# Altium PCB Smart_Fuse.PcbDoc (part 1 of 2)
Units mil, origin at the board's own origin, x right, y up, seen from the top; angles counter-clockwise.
Board outline 4000 x 2763 mil, 4 copper layers (Top Layer, Signal Layer 1, Signal Layer 2, Bottom Layer), stack 61.6 mil thick; 113 components, 65 nets, 281 pads, 450 vias.
Unrouted connection lines stored in the file: 2.
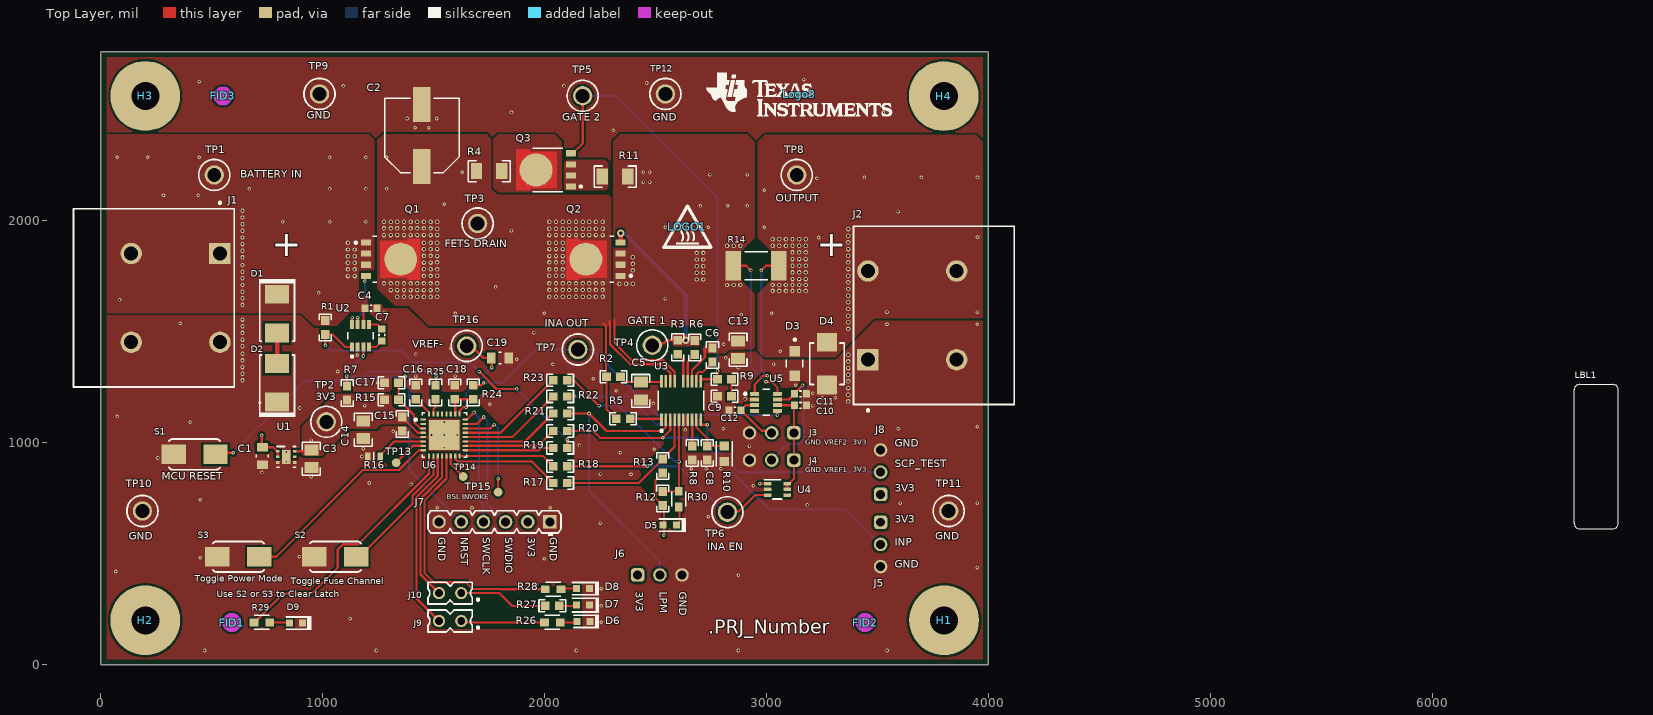
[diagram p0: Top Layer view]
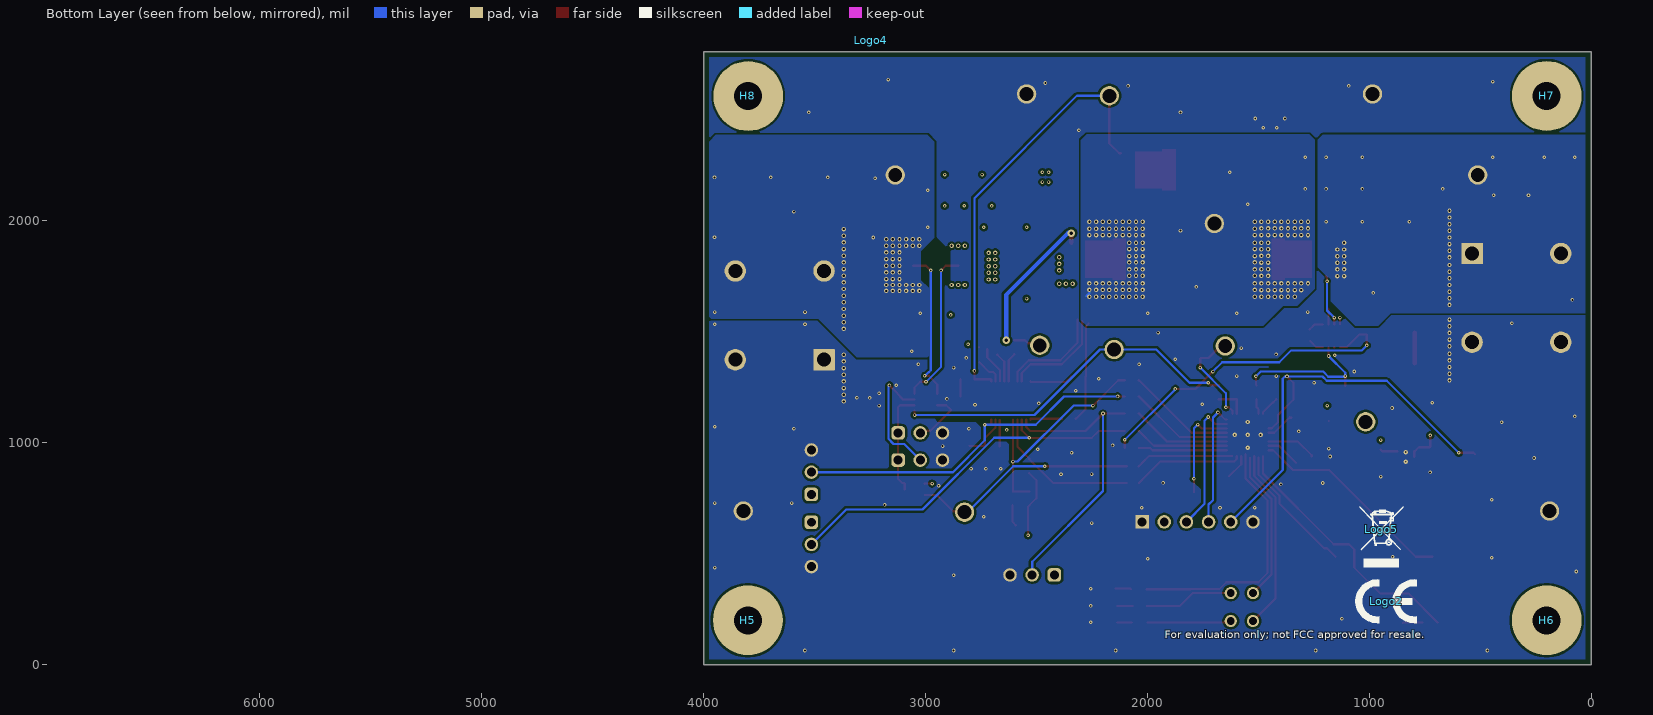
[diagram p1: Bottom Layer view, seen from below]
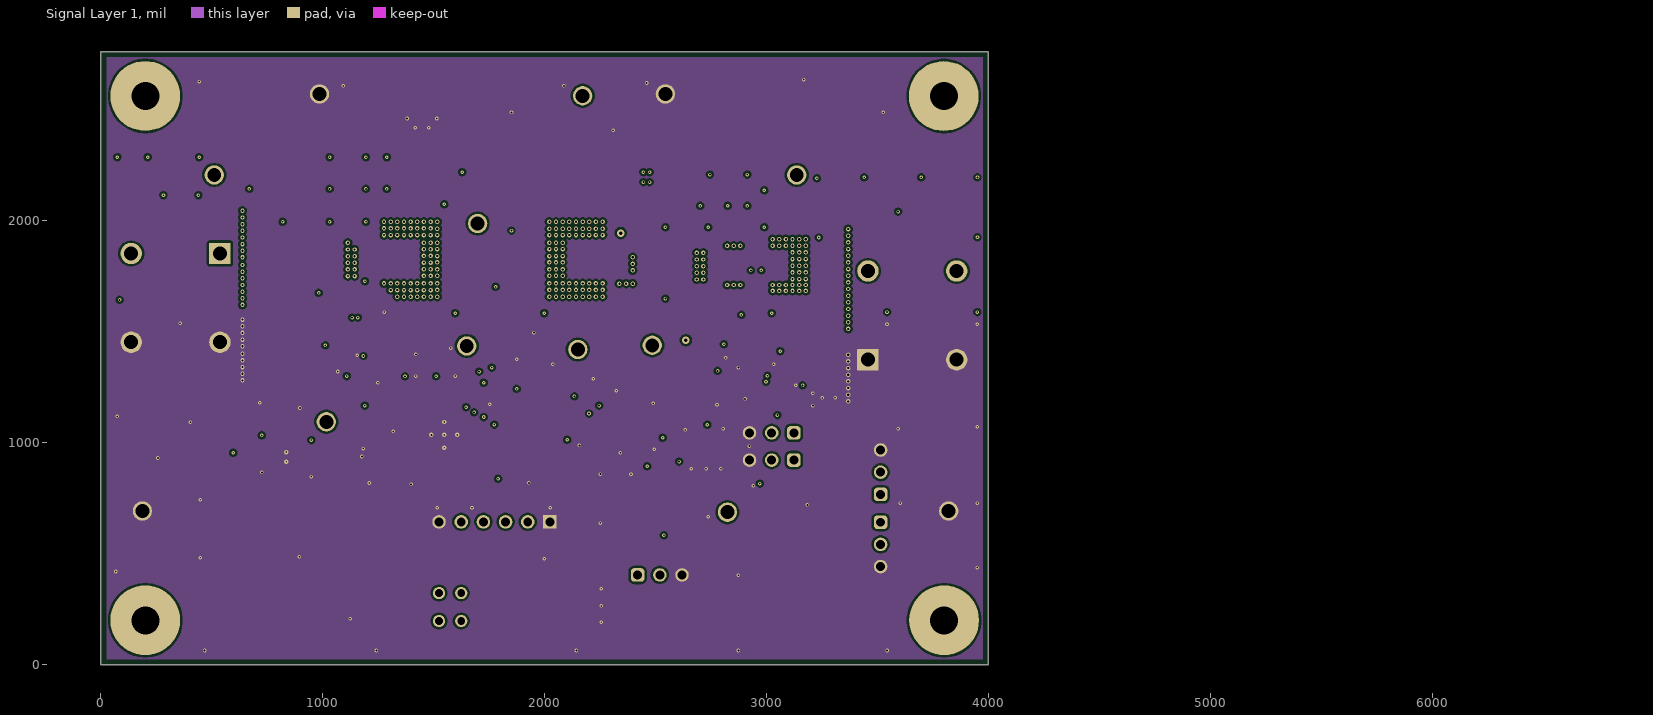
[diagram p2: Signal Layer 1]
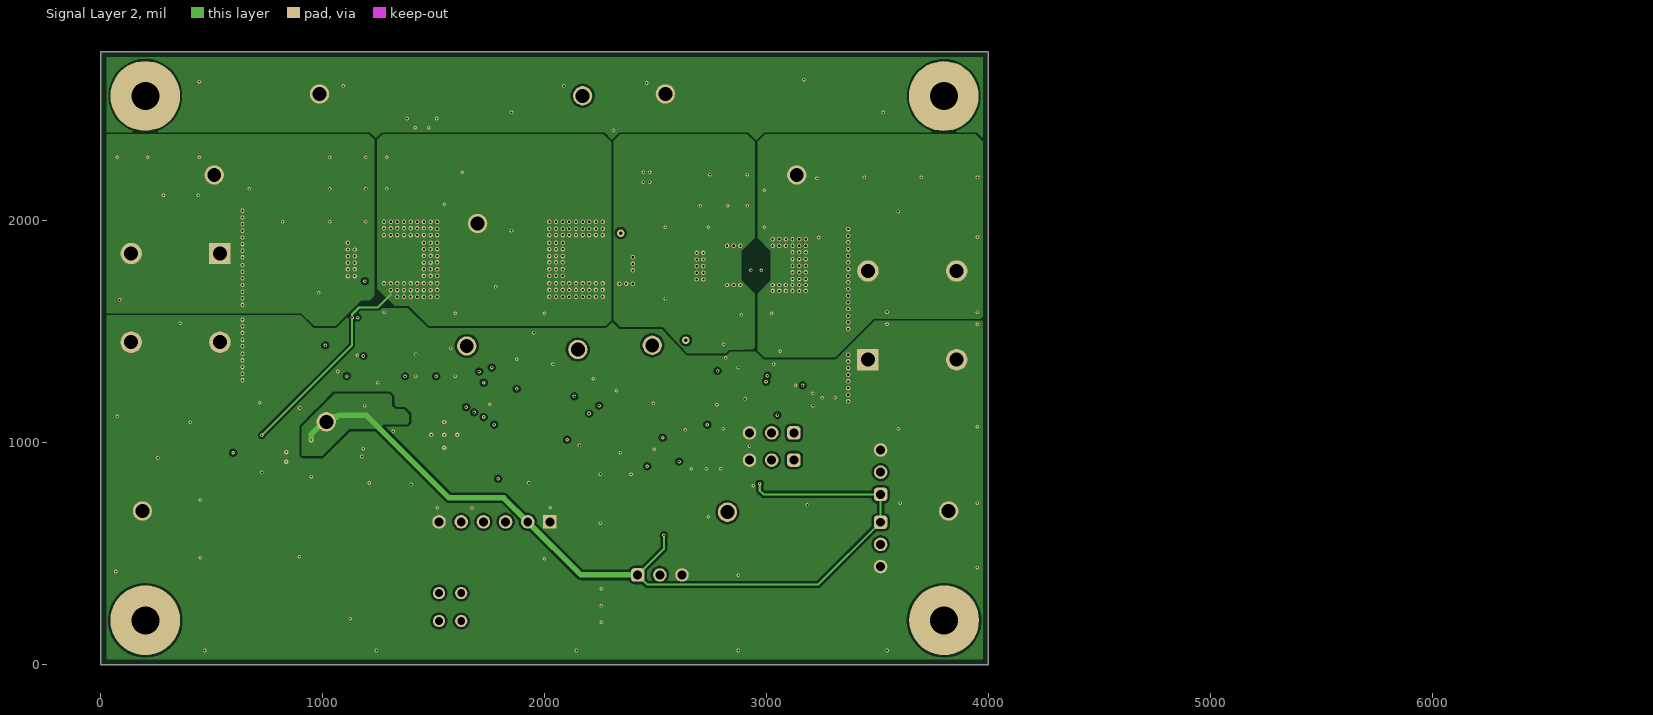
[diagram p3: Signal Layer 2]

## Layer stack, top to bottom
Top Solder: solder mask 0.4, Solder Resist, Dk 3.5
Top Layer: signal copper 2.8
Dielectric 1: prepreg 8, FR-4 High Tg, Dk 4.2
Signal Layer 1: signal copper 1.4
Dielectric 2: core 37.2, FR-4 High Tg, Dk 4.2
Signal Layer 2: signal copper 1.4
Dielectric 3: prepreg 8, FR-4 High Tg, Dk 4.2
Bottom Layer: signal copper 2.8
Bottom Solder: solder mask 0.4, Solder Resist, Dk 3.5

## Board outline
0,0 4000,0 4000,2763 0,2763

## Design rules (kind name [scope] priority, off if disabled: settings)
AcuteAngle [All] p1: minimum=4.50000000000000E+0001 checktracksonly=FALSE
AssemblyTestPointUsage [All] p1: valid=2
BoardOutlineClearance BoardOutlineClearance_MountingHoles [OnCopper and InComponentClass('Mounting Holes')] p1: gap=39.37 ignorepadtopadclearanceinfootprint=FALSE
BoardOutlineClearance BoardOutlineClearance_Poly [OnCopper and IsPoly] p2: gap=25 ignorepadtopadclearanceinfootprint=FALSE
BoardOutlineClearance [OnCopper and Not InComponentClass('Logo') and not InComponentClass('FiducialMark') and not InRegion(1000,500,4000,800) and not InPoly] p3: gap=40 ignorepadtopadclearanceinfootprint=FALSE
Clearance Clearance_Keepouts [((IsTrack Or IsArc) And Not InPoly) And IsFree and IsKeepOut vs ((IsTrack Or IsArc) And Not InPoly) And IsFree and IsKeepOut] p1: gap=0 ignorepadtopadclearanceinfootprint=FALSE
Clearance Clearance_Poly [InPolygon] p2: gap=10 ignorepadtopadclearanceinfootprint=TRUE
Clearance Clearance_FiducialMark [IsKeepOut and InComponentClass('FiducialMark') vs IsPad and InComponentClass('FiducialMark')] p3: gap=0 ignorepadtopadclearanceinfootprint=FALSE
Clearance [All] p4: gap=7.87 ignorepadtopadclearanceinfootprint=TRUE
ComponentClearance ComponentClearance_MountingHoles_FiducialMarks [InComponentClass('Mounting Holes') vs InComponentClass('FiducialMark')] p1: gap=50 collisioncheckmode=3 verticalgap=10 showdistances=FALSE
ComponentClearance ComponentClearance_Shunt [InComponentClass('Header') vs InComponentClass('Shunt')] p2: gap=0 collisioncheckmode=3 verticalgap=0 showdistances=FALSE
ComponentClearance ComponentClearance_Logo [InComponentClass('Logo')] p3: gap=30 collisioncheckmode=3 verticalgap=10 showdistances=FALSE
ComponentClearance ComponentClearance_ScrewToNut [(HasFootprint('NY PMS 440 0025 PH')) vs (HasFootprint('Keystone_1902C'))] p4: gap=5 collisioncheckmode=3 verticalgap=10 showdistances=FALSE
ComponentClearance ComponentClearance_MountingHoles [InComponentClass('Mounting Holes')] p5: gap=100 collisioncheckmode=3 verticalgap=100000 showdistances=FALSE
ComponentClearance ComponentClearance_SmallPassives [HasFootprint('0201*') or HasFootprint('0402*') or HasFootprint('0508') or HasFootprint('0603*') or HasFootprint('0612') or HasFootprint('0805*') or HasFootprint('0815*') or HasFootprint('0830*') or HasFootprint('1206*') or HasFootprint('1210*') or HasFootprint('1808*') or HasFootprint('1812*') or HasFootprint('1825*') or HasFootprint('2010*') or HasFootprint('2220*') or HasFootprint('2225*') or HasFootprint('2512*') or HasFootprint('2728*') or HasFootprint('3518*') vs HasFootprint('0201*') or HasFootprint('0402*') or HasFootprint('0508') or HasFootprint('0603*') or HasFootprint('0612') or HasFootprint('0805*') or HasFootprint('0815*') or HasFootprint('0830*') or HasFootprint('1206*') or HasFootprint('1210*') or HasFootprint('1808*') or HasFootprint('1812*') or HasFootprint('1825*') or HasFootprint('2010*') or HasFootprint('2220*') or HasFootprint('2225*') or HasFootprint('2512*') or HasFootprint('2728*') or HasFootprint('3518*')] p6: gap=14.96 collisioncheckmode=3 verticalgap=10 showdistances=FALSE
ComponentClearance ComponentClearance_THtoSMT [IsThruComponent vs IsSMTComponent] p7: gap=30 collisioncheckmode=3 verticalgap=30 showdistances=FALSE
ComponentClearance ComponentClearance_THtoTH [IsThruComponent vs IsThruComponent] p8: gap=20 collisioncheckmode=3 verticalgap=30 showdistances=FALSE
ComponentClearance [All] p9: gap=20 collisioncheckmode=3 verticalgap=10 showdistances=FALSE
DiffPairsRouting [All] p1: maxlimit=100 minlimit=10 mostfreqgap=10 toplayer_minwidth=15 toplayer_maxwidth=15 toplayer_prefwidth=15 midlayer1_minwidth=15 midlayer1_maxwidth=15 midlayer1_prefwidth=15 midlayer2_minwidth=15 midlayer2_maxwidth=15 midlayer2_prefwidth=15 bottomlayer_minwidth=15 bottomlayer_maxwidth=15 bottomlayer_prefwidth=15 maxuncoupledlength=1000
FabricationTestPointUsage TestPointUsage [All] p1: valid=2 allowmultiple=FALSE
FabricationTestpoint Testpoint [All] p1: side=3 testpointundercomponent=TRUE minsize=40 maxsize=100 preferedsize=60 minholesize=0 maxholesize=40 preferedholesize=32 testpointgrid=1 allowsidetop=TRUE allowsidebottom=TRUE usegrid=TRUE gridtolerance=0.01
FanoutControl Fanout_LCC [IsLCC] p1: bgadir=Out bgaviamode=Centered fanoutstyle=Auto fanoutdirection=Alternating viagrid=1 // Fanout_LCC (Default Rule)
FanoutControl Fanout_BGA [IsBGA] p2: bgadir=Out bgaviamode=Centered fanoutstyle=Auto fanoutdirection=Alternating viagrid=1 // Fanout_BGA (Default Rule)
FanoutControl Fanout_Default [All] p4: bgadir=Out bgaviamode=Centered fanoutstyle=Auto fanoutdirection=Alternating viagrid=1 // Fanout_Default (Default Rule)
FanoutControl Fanout_Small [(CompPinCount < 5)] p5: bgadir=Out bgaviamode=Centered fanoutstyle=Auto fanoutdirection=OutThenIn viagrid=1 // Fanout_Small (Default Rule)
HoleSize [All] p1: absolutevalues=TRUE maxlimit=251 minlimit=7.87 maxpercent=80.000 minpercent=20.000
MinimumAnnularRing MinimumAnnularRing_ThermalPadVias [IsVia and InAnyComponent] p1: minimumring=5.91
MinimumAnnularRing [All] p2: minimumring=4
MinimumSolderMaskSliver MinimumSolderMaskSliver_Logo [InComponentClass('Logo') vs InComponentClass('Logo')] p1: minsoldermaskwidth=0.7
MinimumSolderMaskSliver [All] p2: minsoldermaskwidth=3.94
PlaneConnect [All] p1: planeconnectstyle=Direct reliefexpansion=10 reliefentries=4 reliefconductorwidth=10 reliefairgap=10
PolygonConnect [All] p1: connectstyle=Direct reliefconductorwidth=10 reliefentries=4 polygonreliefangle="90 Angle" airgapwidth=10
RoutingVias ThermalPadVias [IsVia and InAnyComponent] p1: holewidth=7.87 width=19.68 viastyle="Through Hole" minholewidth=7.87 minwidth=19.68 maxholewidth=12.99 maxwidth=23.62
RoutingVias [All] p2: holewidth=8 width=16 viastyle="Through Hole" minholewidth=7 minwidth=8 maxholewidth=40 maxwidth=65
RoutingVias RoutingVias_1 [All] p3: holewidth=28 width=50 viastyle="Through Hole" minholewidth=28 minwidth=50 maxholewidth=28 maxwidth=50
SilkToBoardRegionClearance [Not ((IsComment or IsDesignator) And (Hide <> 'False')) and not InRegion(1000,500,4000,800)] p1:
SilkToSilkClearance SilkToSilkClearance_Pb-FreeLogo [(HasFootprint('Pb-Free_Overlay_Medium') OR HasFootprint('Pb-Free_Overlay_Small')) vs (HasFootprint('Pb-Free_Overlay_Medium') OR HasFootprint('Pb-Free_Overlay_Small'))] p1: silktosilkclearance=0
SilkToSilkClearance [All] p2: silktosilkclearance=3.94
SilkToSolderMaskClearance SilkToComponentPadClearance [(IsPad or IsFill or IsRegion) and InAnycomponent] p1: minsilkscreentomaskgap=5 clearancetoexposedcopper=TRUE
SilkToSolderMaskClearance "Silk to Solder Mask Opening" [All] p2: minsilkscreentomaskgap=3.94 clearancetoexposedcopper=FALSE
SolderMaskExpansion [All] p1: expansion=1.97 istentingtop=FALSE
UnRoutedNet [All] p1: checkbadconnections=TRUE
Width [All] p1: maxlimit=100 minlimit=6 preferedwidth=10
14 further rules are at their usual default settings.

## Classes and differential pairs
component class Smart_Fuse_Schematic: C1 C2 C3 C4 C5 C6 C7 C8 C9 C10 C11 C12 C13 D1 D2 D3 D4 J1 J2 J3 J4 Q1 Q2 Q3 R1 R2 R3 R4 R5 R6 R7 R8 R9 R10 R11 R12 R13 R14 TP1 TP2 TP3 TP4 TP5 TP6 TP7 TP8 TP9 TP10 TP11 TP12 U1 U2 U3 U4 U5
component class Smart_Fuse_MCU_Schematic: C14 C15 C16 C17 C18 C19 D5 D6 D7 D8 D9 J5 J6 J7 J8 J9 J10 R15 R16 R17 R18 R19 R20 R21 R22 R23 R24 R25 R26 R27 R28 R29 R30 S1 S2 S3 TP13 TP14 TP15 TP16 U6
component class Header: J3 J4 J5 J6 J7 J8 J9 J10
component class "Mounting Holes": H1 H2 H3 H4
component class Logo: Logo3
component class Smart_Fuse_Hardware: FID1 FID2 FID3 H1 H2 H3 H4 H5 H6 H7 H8 LBL1 LOGO1 Logo2 Logo3 Logo4 Logo5
component class FiducialMark: FID1 FID2 FID3
component class Label: LBL1

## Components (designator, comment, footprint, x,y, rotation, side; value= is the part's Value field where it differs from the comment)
C1 "UMK212B7105KGHT" FP-UMK212B7105KGHT_0805-MFG 727.34,940.49 r90 top value=1µF
C2 "EEE-FK1J470P" SM_RADIAL_F 1446.85,2385.26 r90 top value=47uF
C3 "GCM21BD70J226ME36L" 0805_HV 948.19,928.19 r270 top value=22uF
C4 "06035C104K4Z4A" 0603L 1216.7,1606.53 r0 top value=0.1uF
C5 "CGA4J2C0G1H223J125AA" 0805_HV 2433.37,1233.76 r270 top value=0.022uF
C6 "06035C104KAZ2A" 0603 2756.27,1395.43 r270 top value=0.1uF
C7 "06035C104K4Z4A" 0603L 1266.63,1486.16 r270 top value=0.1uF
C8 "06035C104KAZ2A" 0603 2732.84,953.78 r270 top value=0.1uF
C9 "CGA3E2X7R1H473K080AA" 0603 2810.66,1209.78 r180 top value=0.047uF
C10 "06035C104KAZ2A" 0603L 3152.84,1168.36 r180 top value=0.1uF
C11 "GRM188R71C104KA01D" 0603L 3152.84,1220.83 r0 top value=0.1uF
C12 "GRM188R71C104KA01D" 0603L 2857.45,1147.57 r180 top value=0.1uF
C13 "CGA4J2C0G1H223J125AA" 0805_HV 2871.84,1419.41 r270 top value=0.022uF
C14 "JMJ212CB7106KGHT" 0805_HV 1182.26,1058.66 r90 top value=10uF
C15 "06035C104KAZ2A" 0603 1358.01,1084.67 r90 top value=0.1uF
C16 "CGA3E3X7R1H474M080AE" 0603 1418.5,1227.38 r90 top value=0.47uF
C17 "C0603C103J3GECAUTO" 0603 1309.28,1270.56 r180 top value=0.01uF
C18 "06035C104KAZ2A" 0603 1595.22,1227.38 r90 top value=0.1uF
C19 "UMK212B7105KGHT" FP-UMK212B7105KGHT_0805-MFG 1798.93,1382.2 r180 top value=1µF
D1 "SMBJ33A-13-F" SMB 793.92,1582.31 r270 top value=33V
D2 "SMBJ16A-13-F" SMB 793.92,1270.56 r90 top value=16V
D3 "PMEG6020ELRX" FP-PMEG6020ELRX_SOD123W-MFG 3126.68,1357.69 r270 top
D4 "SMBJ36CA" FP-SMBJ36CA_DO-214AA-0 3271.96,1356.55 r90 top
D5 "HSMC-C191" HSMx-C191_Red 2563.69,628.5 r0 top value=Red
D6 "LTST-C191KGKT" LTST-C191_Green 2174.49,194.89 r0 top value=Green
D7 "LTST-C193TBKT-5A" LTST-C193_Blue 2172.52,268.45 r0 top value=Blue
D8 "HSMC-C191" HSMx-C191_Red 2172.52,343.17 r0 top value=Red
D9 "LTST-C191KGKT" LTST-C191_Green 878.55,187.28 r0 top value=Green
FID1 "Fiducial" Fiducial10-20#1 590,190 r90 top
FID2 "Fiducial" Fiducial10-20#2 3444,190 r90 top
FID3 "Fiducial" Fiducial10-20#1 550,2563 r90 top
H1 "NY PMS 440 0025 PH" "NY PMS 440 0025 PH"#1 3800,200 r0 top locked
H2 "NY PMS 440 0025 PH" "NY PMS 440 0025 PH"#1 200,200 r0 top locked
H3 "NY PMS 440 0025 PH" "NY PMS 440 0025 PH"#2 200.87,2563.09 r0 top
H4 "NY PMS 440 0025 PH" "NY PMS 440 0025 PH"#3 3800,2563 r0 top
H5 "1902C" Keystone_1902C 3800,200 r180 bottom locked
H6 "1902C" Keystone_1902C 200,200 r180 bottom locked
H7 "1902C" Keystone_1902C 200,2563 r180 bottom
H8 "1902C" Keystone_1902C 3800,2563 r180 bottom
J1 "691256610002" FP-691256610002_HDR2-MFG 239.15,1653.25 r270 top
J2 "691256610002" FP-691256610002_HDR2-MFG 3754.11,1574.35 r90 top
J3 "TSW-103-07-T-S" Samtec_TSW-103-07-T-S 3023.13,1044.67 r180 top
J4 "TSW-103-07-T-S" Samtec_TSW-103-07-T-S 3023.13,922.28 r180 top
J5 "TSW-103-07-T-S" Samtec_TSW-103-07-T-S 3514,542 r270 top
J6 "TSW-103-07-T-S" Samtec_TSW-103-07-T-S 2518.87,404.3 r0 top
J7 "PBC06SAAN" Sullins_PxC06SAAN 1773.8,643.52 r180 top
J8 "TSW-103-07-T-S" Samtec_TSW-103-07-T-S 3514,867.49 r90 top
J9 "SL 11 112 02G" Fischer_SL-11-112-02G 1573.8,196.76 r180 top
J10 "SL 11 112 02G" Fischer_SL-11-112-02G 1573.8,322.67 r180 top
LBL1 "THT-14-423-10" Label_650x200 6739,938 r90 top
LOGO1 "CAUTION HOT SURFACE" IEC_HotSurface_Small 2643.32,1974.33 r0 top
Logo2 "CE Mark" CE_Mark_5mm 924.15,285.69 r180 bottom
Logo3 "Texas Instruments" TI_Stacked_Overlay_Small 3147,2570 r0 top
Logo4 "FCC disclaimer" FCC_disclaimer 3246.69,2814.96 r180 bottom
Logo5 "WEEE logo" WEEE_Minimum 946.02,610.24 r180 bottom
Q1 "BUK7J1R4-40HX" FP-BUK7J1R4-40HX_LFPAK56E-MFG 1317.89,1827.27 r270 top
Q2 "BUK7J1R4-40HX" FP-BUK7J1R4-40HX_LFPAK56E-MFG 2219.09,1827.27 r90 top
Q3 "BUK9Y29-40E,115" FP-BUK9Y29-40E,115_LFPAK56-MFG 2007.78,2229.8 r90 top
R1 "ERJ-3GEY0R00V" 0603 1011.54,1519.79 r90 top value=0
R2 "RMCP0603JT100R" 0603 2310.07,1297.76 r0 top value=100
R3 "ERJ-3GEY0R00V" 0603 2599.52,1430.72 r90 top value=0
R4 "ERJ-8GEY0R00V" 1206 1749.52,2224.48 r180 top value=0
R5 "ERJ-3GEY0R00V" 0603 2353.54,1108.47 r0 top value=0
R6 "ERJ-3GEY0R00V" 0603 2676.11,1429.47 r90 top value=0
R7 "CRCW060314K0FKEA" 0603 1109.45,1224.3 r270 top value=14.0k
R8 "RG1608P-473-B-T5" 0603 2664.82,953.78 r90 top value=47.0k
R9 "CRCW0603220RJNEA" 0603 2810.66,1286.28 r180 top value=220
R10 "ERJ-PB3B1003V" FP-ERJ-PB3B1003V_0603-IPC_A 2809.68,950.68 r270 top value=100k
R11 "CSR1206FKR500" 1206 2317.25,2199.8 r180 top value=0.5
R12 "CRCW060314K0FKEA" 0603 2531.62,748.47 r270 top value=14.0k
R13 "CRCW060314K0FKEA" 0603 2531.62,895.7 r270 top value=14.0k
R14 "WSLF25121L000FEB" FP-WSLF25121L000FEB_2512-MFG 2952.79,1797.74 r180 top
R15 "CRCW060347K0JNEA" 0603 1309.28,1193.89 r180 top value=47k
R16 "ERJ-PB3B1003V" FP-ERJ-PB3B1003V_0603-MFG 1230.63,938.51 r0 top value=100k
R17 "ERJ-3GEY0R00V" 0603 2070,818.83 r180 top value=0
R18 "ERJ-3GEY0R00V" 0603 2070,893.81 r180 top value=0
R19 "ERJ-3GEY0R00V" 0603 2070,976.74 r180 top value=0
R20 "ERJ-3GEY0R00V" 0603 2069.8,1053.17 r180 top value=0
R21 "ERJ-3GEY0R00V" 0603 2069.8,1131.92 r180 top value=0
R22 "ERJ-3GEY0R00V" 0603 2069.8,1208.77 r180 top value=0
R23 "ERJ-3GEY0R00V" 0603 2069.8,1281.53 r180 top value=0
R24 "RG1608P-221-B-T5" 0603 1678.09,1227.38 r270 top value=220
R25 "ERJ-3GEY0R00V" 0603 1508.13,1227.38 r270 top value=0
R26 "RNCF0603TKW1K00" FP-RNCF0603TKW1K00_0603-MFG 2034.37,190.23 r180 top value=1k
R27 "CRCW0603470RJNEA" 0603 2034.37,264.97 r180 top value=470
R28 "RNCF0603TKW1K00" FP-RNCF0603TKW1K00_0603-MFG 2038.31,340.21 r180 top value=1k
R29 "RNCF0603TKW1K00" FP-RNCF0603TKW1K00_0603-MFG 725.37,190.23 r180 top value=1k
R30 "RNCF0603TKW1K00" FP-RNCF0603TKW1K00_0603-MFG 2604,746.43 r270 top value=1k
S1 "147873-2" SW_147873-2 421.99,947.88 r0 top
S2 "147873-2" SW_147873-2 1056.92,486.59 r0 top
S3 "147873-2" SW_147873-2 619.7,486.59 r0 top
TP1 "5010" Keystone5010 510.75,2207.15 r0 top
TP2 "5010" Keystone5010 1015.83,1094.54 r0 top
TP3 "5010" Keystone5010 1697.72,1988.2 r0 top
TP4 "5012" Keystone5012 2484.75,1439.47 r0 top
TP5 "5012" Keystone5012 2171.12,2563.82 r0 top
TP6 "5012" Keystone5012 2823.5,687.29 r0 top
TP7 "5012" Keystone5012 2149.42,1420.34 r0 top
TP8 "5010" Keystone5010 3136,2207.15 r0 top
TP9 "5011" Keystone5011 984.98,2572.31 r0 top
TP10 "5011" Keystone5011 187.01,692.71 r0 top
TP11 "5011" Keystone5011 3820.76,692.71 r0 top
TP12 "5011" Keystone5011 2544,2572.31 r0 top
TP13 "TP_SM_1MM" TP_SM_1MM 1330.35,909.89 r0 top
TP14 "TP_SM_1MM" TP_SM_1MM 1632.47,847.99 r90 top
TP15 "TP_SM_1MM" TP_SM_1MM 1789.96,777.56 r90 top
TP16 "5011" Keystone5011 1648.72,1436.35 r0 top
U1 "TPS7B8133QDRVRQ1" DRV0006A 835.26,936.53 r0 top
U2 "LM74704DDF" DDF0008A-MFG 1170.14,1482.39 r90 top
U3 "TPS12130QDGXRQ1" DGX0019A-MFG 2614.96,1190.45 r90 top
U4 "TPS22919DCKR" DCK0006A_N 3048.68,790.13 r0 top
U5 "INA296B3IDDF" DDF0008A-MFG 2997.5,1182.44 r0 top
U6 "MSPM0L1306SRHB" RHB0032N-MFG 1547.5,1035.47 r0 top

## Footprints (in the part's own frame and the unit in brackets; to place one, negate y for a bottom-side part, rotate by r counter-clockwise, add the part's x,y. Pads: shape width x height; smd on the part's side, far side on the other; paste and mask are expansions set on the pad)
0603 [mm] "0603 from SM-752 data"
  rect 1x0.95 smd: 1(-0.8,0) 2(0.8,0)
  silkscreen extent -1.52,-0.69 1.52,0.69, body extent -0.87,-0.47 0.87,0.47, height 1
0603L [mm] "0603 from SM-752 data"
  rect 0.8x0.85 smd: 1(-0.7,0) 2(0.7,0)
  silkscreen extent -0.07,-0.33 0.07,0.33, body extent -0.87,-0.47 0.87,0.47, height 1
0805_HV [mil] "0805 with 30mil clearance between pads"
  rect 50x63 smd: 1(-40,0) 2(40,0)
  silkscreen extent -74,-40 74,40, body extent -43,-29 43,29, height 57
1206 [mm] "1206 from SM-752 data"
  rect 1.3x1.85 smd: 1(-1.45,0) 2(1.45,0)
  silkscreen extent -2.4,-1.21 2.4,1.21, body extent -1.7,-0.9 1.7,0.9, height 1.35
CE_Mark_5mm [mil] "Minimum text height for CE Mark"
  silkscreen extent -138,-98 138,98
DCK0006A_N [mm] "SOT23, 6-Leads, Body 2x1.3mm, Pitch 0.65mm, Lead Span 2.1mm, IPC Medium Density"
  rrect25% 0.85x0.4 smd: 1(-1.125,0.65) 2(-1.125,0) 3(-1.125,-0.65) 4(1.125,-0.65) 5(1.125,0) 6(1.125,0.65)
  silkscreen extent -1.5,-1.09 0.51,1.09, body extent -1.14,-1 1.14,1, height 0.95
DDF0008A-MFG [mm]
  rrect22% 1.05x0.45 smd paste+0 mask+0: 1(-1.3,0.975) 2(-1.3,0.325) 3(-1.3,-0.325) 4(-1.3,-0.975) 5(1.3,-0.975) 6(1.3,-0.325) 7(1.3,0.325) 8(1.3,0.975)
  silkscreen extent -2.5,-1.48 0.4,1.48, body extent -1.92,-1.73 1.92,1.73, height 0.25
DGX0019A-MFG [mm]
  rrect33% 1.45x0.3 smd paste+0 mask+0: 1(-2.2,2.25) 2(-2.2,1.75) 3(-2.2,1.25) 4(-2.2,0.75) 5(-2.2,0.25) 6(-2.2,-0.25) 7(-2.2,-0.75) 8(-2.2,-1.25) 9(-2.2,-1.75) 10(-2.2,-2.25) 11(2.2,-2.25) 12(2.2,-1.75) 13(2.2,-1.25) 14(2.2,-0.75) 15(2.2,-0.25) 17(2.2,0.75) 18(2.2,1.25) 19(2.2,1.75) 20(2.2,2.25)
  silkscreen extent -3.6,-2.6 1.1,2.6, body extent -3.03,-2.85 3.03,2.85, height 0.25
DRV0006A [mm] "SON, 6-Leads, Body 2x2mm, Pitch 0.65mm, Thermal Pad 1.6x1mm, TI Recommended"
  rrect33% 0.45x0.3 smd: 1(-0.975,0.65) 2(-0.975,0) 3(-0.975,-0.65) 4(0.975,-0.65) 5(0.975,0) 6(0.975,0.65)
  rrect14% 1x0.7 on Top Paste: 7(0,-0.45) 7(0,0.45)
  rrect10% 1x1.6 smd paste-0.5: 7(0,0)
  silkscreen extent -1.05,-1.2 1.05,1.2, body extent -1.05,-1.05 1.05,1.05, height 0.81
FCC_disclaimer [mil]
Fiducial10-20#1 [mm]
  round 1 smd mask+0.5: 1(0,0)
  Top Layer keep-out circle w1.178: c0,0 r0.5
Fiducial10-20#2 [mm]
  round 0.991 smd mask+0.5: 1(0,0)
  Top Layer keep-out circle w1.178: c0,0 r0.5
Fischer_SL-11-112-02G [mm] "TH, 2-Leads, Body 2.5x5.08mm, Pitch 2.54mm"
  round 1.4 hole 0.9: 1(-1.27,0) 2(1.27,0)
  silkscreen extent -3.32,-1.25 2.54,1.25, body extent -2.54,-1.25 2.54,1.25, height 8.4
FP-691256610002_HDR2-MFG [mm]
  rrect4% 2.45x2.45 hole 1.6 paste-1000 mask+0: 1(-5.08,7.55)
  round 2.45 hole 1.6 paste-1000 mask+0: 1(-5.08,-2.61) 2(5.08,7.55) 2(5.08,-2.61)
  silkscreen extent -11,-9.2 10.21,9.2, body extent -10.31,-9.3 10.31,9.3, height 0.25
FP-BUK7J1R4-40HX_LFPAK56E-MFG [mm]
  rrect14% 0.7x1.15 smd paste-1000 mask+0: 1(-1.905,-3.137) 2(-0.635,-3.137) 3(0.635,-3.137) 4(1.905,-3.137)
  round 3.78 smd paste-1000 mask+0: 5(0,0.845)
  Top Layer region: -2.35,3.087 2.35,3.087 2.35,1.587 2.1,1.587 2.1,-1.512 -2.1,-1.512 -2.1,1.587 -2.35,1.587
  silkscreen extent -2.65,-4.42 2.65,-1.89, body extent -2.9,-3.81 2.9,3.19, height 0.25
FP-BUK9Y29-40E,115_LFPAK56-MFG [mm]
  rrect14% 0.7x1.15 smd paste-1000 mask+0: 1(-1.905,-2.8) 2(-0.635,-2.8) 3(0.635,-2.8) 4(1.905,-2.8)
  round 3.78 smd paste-1000 mask+0: 5(0,1.183)
  Top Layer region: -2.35,3.425 2.35,3.425 2.35,1.925 2.1,1.925 2.1,-1.175 -2.1,-1.175 -2.1,1.925 -2.35,1.925
  silkscreen extent -2.5,-4.06 2.5,1.55, body extent -2.75,-3.47 2.75,3.52, height 0.25
FP-ERJ-PB3B1003V_0603-IPC_A [mil]
  rrect9% 41.62x41.82 smd paste+0 mask+0: 1(-35.45,0) 2(35.45,0)
  silkscreen extent -56,-37 56,37, body extent -76,-41 76,41, height 10
FP-ERJ-PB3B1003V_0603-MFG [mm]
  rrect15% 0.65x0.9 smd paste+0 mask+0: 1(-0.725,0) 2(0.725,0)
  silkscreen extent 0,-0.48 0,0.48, body extent -1.15,-0.58 1.15,0.58, height 0.25
FP-PMEG6020ELRX_SOD123W-MFG [mm]
  rrect8% 1.2x1.2 smd paste-1000 mask+0: 1(-1.4,0) 2(1.4,0)
  silkscreen extent -2.85,-0.95 0.43,0.95, body extent -2.2,-1.05 2.2,1.05, height 0.25
FP-RNCF0603TKW1K00_0603-MFG [mm]
  rrect11% 1x0.9 smd paste+0 mask+0: 1(-0.9,0) 2(0.9,0)
  silkscreen extent -0.85,-0.8 0.85,0.8, body extent -1.5,-0.55 1.5,0.55, height 0.25
FP-SMBJ36CA_DO-214AA-0 [mm]
  rrect5% 2.16x2.26 smd paste+0 mask+0: 1(-2.45,0) 2(2.45,0)
  silkscreen extent -2.37,-1.97 2.37,1.97, body extent -3.63,-2.07 3.63,2.07, height 0.25
FP-UMK212B7105KGHT_0805-MFG [mm]
  rrect10% 1x1.25 smd paste+0 mask+0: 1(-1,0) 2(1,0)
  silkscreen extent -0.13,-0.67 0.13,0.67, body extent -1.6,-0.77 1.6,0.77, height 0.25
FP-WSLF25121L000FEB_2512-MFG [mm]
  rrect6% 1.8x3.4 smd paste+0 mask+0: 1(-2.6,0) 2(2.6,0)
  silkscreen extent -1.33,-1.61 1.33,1.61, body extent -3.6,-1.8 3.6,1.8, height 0.25
HSMx-C191_Red [mm] "SMD, 2-Leads, Body 1.6x0.8mm"
  rrect12% 0.8x0.8 smd: 1(-0.75,0) 2(0.75,0)
  silkscreen extent -1.2,-0.8 1.85,0.8, body extent -0.85,-0.45 0.85,0.45, height 0.7
IEC_HotSurface_Small [mil]
  silkscreen extent -107,-93 107,92
Keystone5010 [mil] "Keystone Multipurpose loops"
  round 87 hole 63: 1(0,0)
  silkscreen extent -70,-70 70,70, body extent -63,-63 63,62, height 319
Keystone5011 [mil] "Keystone Multipurpose loops"
  round 87 hole 63: 1(0,0)
  silkscreen extent -70,-70 70,70, body extent -63,-63 63,62, height 319
Keystone5012 [mil] "Keystone Multipurpose loops"
  round 87 hole 63: 1(0,0)
  silkscreen extent -70,-70 70,70, body extent -63,-63 63,62, height 319
Keystone_1902C [mil] "Hex Standoff, 4-40 threaded, nylon"
  round 1 on Mech4: 0(0,0)
  body extent -145,-126 146,126, height 501
Label_650x200 [mil] "Thermal Transfer Label"
  round 1 on Mech13: 0(0,0)
  silkscreen extent -325,-100 325,100, body extent -325,-100 325,100, height 1
LTST-C191_Green [mm] "Lite-On"
  rect 0.8x0.8 smd: 1(-0.75,0) 2(0.75,0)
  silkscreen extent -1.1,-0.8 1.8,0.8, body extent -0.85,-0.45 0.85,0.45, height 0.65
LTST-C193_Blue [mm] "SMD, 2-Leads, Body1.6x0.8mm"
  rect 0.8x0.8 smd: 1(-0.75,0) 2(0.75,0)
  silkscreen extent -1.2,-0.9 1.85,0.9, body extent -0.85,-0.45 0.85,0.45, height 0.45
"NY PMS 440 0025 PH"#1 [mm] "4-40 nylon screw and mounting hole"
  round 8 hole 3.2: 1(0,0)
  body extent -3.3,-3.3 3.3,3.3, height 2.69
"NY PMS 440 0025 PH"#2 [mm] "4-40 nylon screw and mounting hole"
  round 8 hole 3.2: 1(-0.022,-0.002)
  body extent -3.3,-3.3 3.3,3.3, height 2.69
"NY PMS 440 0025 PH"#3 [mm] "4-40 nylon screw and mounting hole"
  round 8 hole 3.2: 1(-0.034,-0.005)
  body extent -3.3,-3.3 3.3,3.3, height 2.69
RHB0032N-MFG [mm]
  rrect40% 0.6x0.25 smd paste+0 mask+0: 1(-2.4,1.75) 2(-2.4,1.25) 3(-2.4,0.75) 4(-2.4,0.25) 5(-2.4,-0.25) 6(-2.4,-0.75) 7(-2.4,-1.25) 8(-2.4,-1.75) 17(2.4,-1.75) 18(2.4,-1.25) 19(2.4,-0.75) 20(2.4,-0.25) 21(2.4,0.25) 22(2.4,0.75) 23(2.4,1.25) 24(2.4,1.75)
  rrect40% 0.25x0.6 smd paste+0 mask+0: 9(-1.75,-2.4) 10(-1.25,-2.4) 11(-0.75,-2.4) 12(-0.25,-2.4) 13(0.25,-2.4) 14(0.75,-2.4) 15(1.25,-2.4) 16(1.75,-2.4) 25(1.75,2.4) 26(1.25,2.4) 27(0.75,2.4) 28(0.25,2.4) 29(-0.25,2.4) 30(-0.75,2.4) 31(-1.25,2.4) 32(-1.75,2.4)
  rrect3% 3.45x3.45 smd paste-1000 mask+0: 33(0,0)
  silkscreen extent -3.4,-2.55 2.55,2.55, body extent -2.8,-2.8 2.8,2.8, height 0.25
Samtec_TSW-103-07-T-S [mm] "Header, 2.54 mm, 3x1, TH"
  rrect50% 1.55x1.55 hole 1.02: 1(-2.54,0)
  round 1.55 hole 1.02: 2(0,0) 3(2.54,0)
  body extent -3.81,-1.27 3.81,1.27, height 8.39
SM_RADIAL_F [mm] "8 x 10.2mm:  Panasonic F"
  rect 4x2 smd: 1(-3.55,0) 2(3.55,0)
  silkscreen extent -4.25,-4.25 4.25,4.25, body extent -4.25,-4.25 4.25,4.25, height 10.5
SMB [mil] "Molded Diode, 2-Leads, Body 5.4x3.6mm, IPC Medium Density, based on OnSemi component dimensions"
  rect 85x107.99 smd: 1(-87.01,0) 2(87.01,0)
  silkscreen extent -155,-82 125,82, body extent -106,-71 106,71, height 91
Sullins_PxC06SAAN [mm] "Header, 2.54mm, 6x1, TH"
  rect 1.55x1.55 hole 1.016: 1(-6.35,0)
  round 1.55 hole 1.016: 2(-3.81,0) 3(-1.27,0) 4(1.27,0) 5(3.81,0) 6(6.35,0)
  silkscreen extent -7.62,-1.27 7.62,1.6, body extent -7.62,-1.27 7.62,1.27, height 8.38
SW_147873-2 [mm] "SMD, 2-Leads, Body 6x3.5mm"
  rect 2.8x2.2 smd: 1(-2.4,0) 2(2.4,0)
  silkscreen extent -2.93,-1.75 2.93,1.75, body extent -3.4,-1.75 3.4,1.75, height 4.5
TI_Stacked_Overlay_Small [mil]
  silkscreen extent -418,-98 418,98
TP_SM_1MM [mm] "1mm Test Point, SMT"
  round 1 smd paste-0.5: 1(0,0)
WEEE_Minimum [mil] "WEEElie bin"
  silkscreen extent -95,-172 99,104

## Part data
C1 C19: library part CMP-0098253-1, "Multilayer Ceramic Capacitor 1 uF 50V X7R 10% SMD 0805 Automotive T/R", Manufacturer="Taiyo Yuden", Operating Temperature Range="-55°C to +125°C", TempCo=0.15, Temperature Characteristic=X7R, Tolerance_%=0.1%, ValueDisplayed=1uF
C2: library part CMP-0011192-2, "CAP, AL, 47 uF, 63 V, +/- 20%, 0.65 ohm, AEC-Q200 Grade 2, SMD", Cap_Case=F, Manufacturer=Panasonic, Supplier Part Number 1=PCE3823CT-ND, Tolerance_%=20%, Value1="0.65 ohm", Value2=63V, ValueDisplayed=47uF
C3: library part CMP-0008015-1, "CAP, CERM, 22 uF, 6.3 V, +/- 20%, X7T, AEC-Q200 Grade 1, 0805", Cap_Case=0805, Manufacturer=MuRata, TempCo=X7T, Tolerance_%=20%, Value1=Unknown, Value2=6.3V, ValueDisplayed=22uF
C4 C7: library part CMP-0084736-1, "CAP, CERM, 0.1 µF, 50 V,+/- 10%, X7R, AEC-Q200 Grade 0, 0603", Cap_Case=0603, Manufacturer=AVX, TempCo=X7R, Tolerance_%=10%, Value2=50V, ValueDisplayed=0.1µF
C5 C13: library part CMP-0079608-1, "CAP, CERM, 0.022 µF, 50 V,+/- 5%, C0G/NP0, AEC-Q200 Grade 1, 0805", Cap_Case=0805, Manufacturer=TDK, Supplier Part Number 1=445-6949-1-ND, TempCo=C0G/NP0, Tolerance_%=5%, Value2=50V, ValueDisplayed=0.022µF
C6 C8 C10 C15 C18: library part CMP-0079095-1, "CAP, CERM, 0.1 µF, 50 V,+/- 10%, X7R, AEC-Q200 Grade 1, 0603", Cap_Case=0603, Manufacturer=AVX, Supplier Part Number 1=478-3540-1-ND, TempCo=X7R, Tolerance_%=10%, Value2=50V, ValueDisplayed=0.1µF
C9: library part CMP-0007079-4, "CAP, CERM, 0.047 uF, 50 V, +/- 10%, X7R, AEC-Q200 Grade 1, 0603", Cap_Case=0603, Manufacturer=TDK, Supplier Part Number 1=445-5664-1-ND, TempCo=X7R, Tolerance_%=10%, Value1="0.049007 ohm", Value2=50V, ValueDisplayed=0.047uF
C11 C12: library part CMP-0007378-5, "CAP, CERM, 0.1 uF, 16 V, +/- 10%, X7R, 0603", Cap_Case=0603, Manufacturer=MuRata, Supplier Part Number 1=490-1532-1-ND, TempCo=X7R, Tolerance_%=10%, Value1=Unknown, Value2=16V, ValueDisplayed=0.1uF
C14: library part CMP-0081188-1, "CAP, CERM, 10 µF, 6.3 V,+/- 10%, X7R, AEC-Q200 Grade 1, 0805", Cap_Case=0805, Manufacturer="Taiyo Yuden", Supplier Part Number 1=587-4357-1-ND, TempCo=X7R, Tolerance_%=10%, Value2=6.3V, ValueDisplayed=10µF
C16: library part CMP-0007098-4, "CAP, CERM, 0.47 uF, 50 V, +/- 20%, X7R, AEC-Q200 Grade 1, 0603", Cap_Case=0603, Manufacturer=TDK, Supplier Part Number 1=445-172476-1-ND, TempCo=X7R, Tolerance_%=20%, Value1=Unknown, Value2=50V, ValueDisplayed=0.47uF
C17: library part CMP-0006849-4, "CAP, CERM, 0.01 uF, 25 V, +/- 5%, C0G/NP0, AEC-Q200 Grade 1, 0603", Cap_Case=0603, Manufacturer=Kemet, Supplier Part Number 1=399-14102-1-ND, TempCo=C0G/NP0, Tolerance_%=5%, Value1=Unknown, Value2=25V, ValueDisplayed=0.01uF
D1: library part CMP-0005563-4, "Diode, TVS, Uni, 33 V, 53.3 Vc, SMB", Manufacturer="Diodes Inc.", Value1=600W
D2: library part CMP-0005547-4, "Diode, TVS, Uni, 16 V, 26 Vc, SMB", Manufacturer="Diodes Inc.", Value1=600W
D3: library part CMP-0090247-1, "Diode Schottky 60V 2A Surface Mount CFP3", Digikey Part Number=1727-2298-1-ND, Forward Current=2.83A, Manufacturer=Nexperia, Max Surge Forward Current=50A, Mouser Part Number=771-PMEG6020ELRX, Operating Temperature Range="to +175°C", Peak Reverse Current=0.09uA, ValueDisplayed=110pF
D4: library part CMP-0086728-1, "Diode TVS Single Bi-Dir 36V 600W 2-Pin SMB", Manufacturer=Littelfuse
D5 D8: library part CMP-0078541-2, "LED, Red, SMD", Color=Red, Manufacturer=Avago, Value1=W, Value2=1.9V
D6 D9: library part CMP-0078478-2, "LED, Green, SMD", Color=Green, Manufacturer=Lite-On, Power_TotalModule=75mW, Value1=0.075W, Value2=2V
D7: library part CMP-0002938-3, "LED, Blue, SMD", Color=Blue, Manufacturer=Lite-On, Power_TotalModule=76mW, Value1=0.076W, Value2=2.8V
FID1 FID2 FID3: library part CMP-0077181-1, "Fiducial mark.  There is nothing to buy or mount.", Manufacturer=N/A
H1 H2 H3 H4: library part CMP-0003617-1, "Machine Screw, Round, #4-40 x 1/4, Nylon, Philips panhead", Manufacturer="B&F Fastener Supply", Supplier Part Number 1=H542-ND
H5 H6 H7 H8: library part CMP-0003610-1, "Standoff, Hex, 0.5\"L #4-40 Nylon", Manufacturer=Keystone, Supplier Part Number 1=36-1902C-ND
J1 J2: library part CMP-0086764-1, "2 Position Wire to Board Terminal Block Horizontal with Board 0.400\" (10.16mm) Through Hole", Current_A=57A, Manufacturer=Wurth, Voltage_V=750V
J3 J4 J5 J6 J8: library part CMP-0075530-2, "Header, 2.54 mm, 3x1, Tin, TH", Color=Black, Current_A=6.3A, Manufacturer=Samtec, Supplier Part Number 1=SAM1035-03-ND, Voltage_V=550V
J7: library part CMP-0054603-1, "Header, 2.54mm, 6x1, Gold, TH", Color=Black, Current_A=3A, Manufacturer="Sullins Connector Solutions", Supplier Part Number 1=S1011E-06-ND
J9 J10: library part CMP-0075049-1, "Header, 2.54mm, 2x1, Gold, TH", Manufacturer="Fischer Elektronik"
LBL1: library part CMP-0003625-1, "Thermal Transfer Printable Labels, 0.650\" W x 0.200\" H - 10,000 per roll", Manufacturer=Brady, Supplier Part Number 1=97C5133
LOGO1: library part CMP-0074837-1, "IEC 61010-1 Hot Surface Warning"
Logo2: library part CMP-0074844-1
Logo3: library part CMP-0074838-1, "Texas Instrument Corporate Signature"
Logo4: library part CMP-0074847-1, "FCC_disclaimer"
Logo5: library part CMP-0074769-1
Q1 Q2: library part CMP-0098150-1, "Trans MOSFET N-CH 40V 190A Automotive 5-Pin(4+Tab) LFPAK T/R", Digikey Part Number=1727-7419-1-ND, Drain To Source Breakdown Voltage=42V, Input Capacitace At Vds="5436pF @ 25V", Manufacturer=Nexperia, Mouser Part Number=771-BUK7J1R4-40HX, Operating Temperature Range="-55°C to +175°C", Power_W=395W, Pulse Drain Current=600A, Typ Forward Diode Voltage=0.8V
Q3: library part CMP-0098178-1, "Trans MOSFET N-CH 40V 25A Automotive 5-Pin(4+Tab) LFPAK T/R", Digikey Part Number=1727-1497-1-ND, Drain To Source Breakdown Voltage=40V, Input Capacitace At Vds="498pF @ 25V", Manufacturer=Nexperia, Mouser Part Number=771-BUK9Y29-40E115, Operating Temperature Range="-55°C to +175°C", Power_W=37W, Pulse Drain Current=101A, Typ Forward Diode Voltage=0.84V
R1 R3 R5 R6 R17 R18 R19 R20 R21 R22 R23 R25: library part CMP-0025874-4, "RES, 0, 5%, 0.1 W, AEC-Q200 Grade 0, 0603", Manufacturer=Panasonic, Power_W=100mW, Supplier Part Number 1=P0.0GCT-ND, TempCo="600 ppm/C", Tolerance_%=5%, Value2=0.1W, Value_Code=0000, ValueDisplayed=0
R2: library part CMP-0860543-1, "RES, 100, 5%, 0.25 W, AEC-Q200 Grade 0, 0603", Manufacturer="Stackpole Electronics Inc", Power_W=250mW, TempCo="100 ppm/C", Tolerance_%=5%, Value2=0.25W, Value_Code=100R, ValueDisplayed=100
R4: library part CMP-0018748-3, "RES, 0, 5%, 0.25 W, AEC-Q200 Grade 0, 1206", Manufacturer=Panasonic, Power_W=250mW, Supplier Part Number 1=P0.0ECT-ND, TempCo="600 ppm/C", Tolerance_%=5%, Value2=0.25W, Value_Code=0000, ValueDisplayed=0
R7 R12 R13: library part CMP-0022054-4, "RES, 14.0 k, 1%, 0.1 W, AEC-Q200 Grade 0, 0603", Manufacturer=Vishay-Dale, Power_W=100mW, Supplier Part Number 1=541-14.0KHCT-ND, TempCo="100 ppm/C", Tolerance_%=1%, Value2=0.1W, Value_Code=14k0, ValueDisplayed=14.0k
R8: library part CMP-0023556-3, "RES, 47.0 k, 0.1%, 0.1 W, 0603", Manufacturer="Susumu Co Ltd", Power_W=100mW, Supplier Part Number 1=RG16P47.0KBCT-ND, TempCo="25 ppm/C", Tolerance_%=0.1%, Value2=0.1W, Value_Code=47k0, ValueDisplayed=47.0k
R9: library part CMP-0025756-4, "RES, 220, 5%, 0.1 W, AEC-Q200 Grade 0, 0603", Manufacturer=Vishay-Dale, Power_W=100mW, Supplier Part Number 1=541-220GCT-ND, TempCo="200 ppm/C", Tolerance_%=5%, Value2=0.1W, Value_Code=220R, ValueDisplayed=220
R10 R16: library part CMP-0092407-1, "Res Thick Film 0603 100K Ohm 0.1% 0.2W(1/5W) ±50ppm/°C Pad SMD Automotive T/R", Digikey Part Number=P20200CT-ND, Manufacturer=Panasonic, Mouser Part Number=667-ERJ-PB3B1003V, Operating Temperature Range="-55°C to +155°C", Power_W=200mW, TempCo=50ppm/°C, Tolerance_%=0.1%
R11: library part CMP-0017270-2, "RES, 0.5, 1%, 0.5 W, 1206", Manufacturer="Stackpole Electronics Inc", Power_W=500mW, Supplier Part Number 1=CSR1206FKR500CT-ND, TempCo="100 ppm/C", Tolerance_%=1%, Value2=0.5W, Value_Code=R500, ValueDisplayed=0.5
R14: library part CMP-0089827-1, "1 mOhms ±1% 5W Chip Resistor 2512 (6432 Metric) Automotive AEC-Q200, Current Sense, Moisture Resistant, Pulse Withstanding Metal Element", Digikey Part Number=541-3130-1-ND, Manufacturer=Vishay, Mouser Part Number=71-WSLF25121L000FEB, Operating Temperature Range="-65°C to +170°C", Power_W=5W, TempCo=170ppm/°C, Tolerance_%=1%
R15: library part CMP-0025814-4, "RES, 47 k, 5%, 0.1 W, AEC-Q200 Grade 0, 0603", Manufacturer=Vishay-Dale, Power_W=100mW, Supplier Part Number 1=541-47KGCT-ND, TempCo="200 ppm/C", Tolerance_%=5%, Value2=0.1W, Value_Code=47k0, ValueDisplayed=47k
R24: library part CMP-0023472-3, "RES, 220, 0.1%, 0.1 W, 0603", Manufacturer="Susumu Co Ltd", Power_W=100mW, Supplier Part Number 1=RG16P220BCT-ND, TempCo="25 ppm/C", Tolerance_%=0.1%, Value2=0.1W, Value_Code=220R, ValueDisplayed=220
R26 R28 R29 R30: library part CMP-0091933-1, "1 kOhms ±0.01% 0.1W, 1/10W Chip Resistor 0603 (1608 Metric) Automotive AEC-Q200 Thin Film", Digikey Part Number=738-RNCF0603TKW1K00CT-ND, Manufacturer="Stackpole Electronics", Operating Temperature Range="-55°C to +155°C", Power_W=100mW, TempCo=2ppm/°C, Tolerance_%=0.01%
R27: library part CMP-0025813-4, "RES, 470, 5%, 0.1 W, AEC-Q200 Grade 0, 0603", Manufacturer=Vishay-Dale, Power_W=100mW, Supplier Part Number 1=541-470GCT-ND, TempCo="200 ppm/C", Tolerance_%=5%, Value2=0.1W, Value_Code=470R, ValueDisplayed=470
S1 S2 S3: library part CMP-0002294-1, "Switch, SPST, Off-On, 50 mA,24V, SMD", CurrentRating_mA=50A, Manufacturer="TE Connectivity", Supplier Part Number 1=450-2049-1-ND
TP1 TP2 TP3 TP8: library part CMP-0055147-2, "Test Point, Multipurpose, Red, TH", Color=Red, Manufacturer="Keystone Electronics", Supplier Part Number 1=36-5010-ND
TP4 TP5 TP6 TP7: library part CMP-0055149-2, "Test Point, Multipurpose, White, TH", Color=White, Manufacturer="Keystone Electronics", Supplier Part Number 1=36-5012-ND
TP9 TP10 TP11 TP12 TP16: library part CMP-0055148-2, "Test Point, Multipurpose, Black, TH", Color=Black, Manufacturer="Keystone Electronics", Supplier Part Number 1=36-5011-ND
TP13 TP14 TP15: library part CMP-0003825-1, "1mm Test Point, SMT", Manufacturer=Any
U1: library part CMP-0860463-2, "Automotive 150-mA high-voltage ultra-low-IQ low-dropout (LDO) linear regulator, DRV0006A (WSON-6)", Alternate Manufacturer="Texas Instruments", Operating Temperature Range="-40 to 150 C", Rating=Automotive
U2: library part CMP-0097715-1, "Ideal Diode Controller with FET Good Output, SOT23-8", Manufacturer="Texas Instruments", Max Supply Voltage=60V, Min Supply Voltage=4V, Nominal Supply Current=80uA, Operating Temperature Range="-40°C to +150°C"
U3: library part CMP-0098484-1, "45-V Low IQ Automotive High Side Switch Controller with Low Power Mode and Adjustable Load Wakeup Trigger", Manufacturer="Texas Instruments", Max Supply Voltage=40V, Min Supply Voltage=3V, Nominal Supply Current=28-36uA, Operating Temperature Range="-40°C to +150°C"
U4: library part CMP-0081108-1, "5.5-V, 1.5-A, 100-mohm Load Switch with Output Discharge, DCK0006A (SOT-SC70-6)", Alternate Manufacturer="Texas Instruments", Alternate PartNumber=TPS22919DCKT
U5: library part CMP-0096516-2, "-4-V to 110-V, Bidirectional, 1-MHz, 5-V/μs, Ultra-Precise Current Sense Amplifier", Input Bias Current=40uA, Input Offset Voltage=0.025mV, Manufacturer="Texas Instruments", Max Supply Voltage=20V, Min Supply Voltage=2.7V, Nominal Supply Current=2.5mA, Operating Temperature Range="-40°C to +125°C", Voltage Gain=0.05V/mV
U6: library part CMP-0093968-1, "MSPM0L130x Mixed-Signal Microcontrollers", Frequency_Fixed=32MHz, Manufacturer="Texas Instruments", Max Supply Voltage=3.6V, Min Supply Voltage=1.62V, Operating Temperature Range="-40°C to +125°C"

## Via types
v1: diameter 20, hole 10, Top Layer to Bottom Layer, 262 vias
v2: diameter 16, hole 8, Top Layer to Bottom Layer, tented both sides, 179 vias
v3: diameter 19.68, hole 7.87, Top Layer to Bottom Layer, 7 vias
v4: diameter 34, hole 16, Top Layer to Bottom Layer, tented both sides, 2 vias

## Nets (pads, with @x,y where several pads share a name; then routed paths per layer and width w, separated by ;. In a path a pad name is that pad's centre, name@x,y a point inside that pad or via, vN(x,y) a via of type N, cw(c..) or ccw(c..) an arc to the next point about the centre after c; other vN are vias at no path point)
"3V3 LDO": C3.1 C14.2 C15.2 D5.1 J5.1 J6.1 J7.2 J8.1 R7.2 R12.2 R13.2 R15.2 TP2.1 U1.6 U4.1 U6.4 | length 4551.7
  Top Layer w10: U1.6@873.64,962.12 942.12,962.12 C3.1@948.19,968.19 ; C15.2@1350.78,1112.76 C15.2@1358.01,1112.76 ; C15.2@1358.01,1116.17 1358.01,1115.18 1427.88,1045.31 U6.4@1453.01,1045.31 U6.4@1452.93,1045.39 ; R13.2@2531.62,864.2 2531.62,863.22 2500.04,831.64 2500.04,749.53 2531.62,717.96 R12.2@2531.62,716.97 2537.58,711.01 D5.1@2537.58,632.39 ; v2(2537.4,583.19) D5.1@2537.4,633.01 ; v2(2969.7,816.13) 2969.9,815.93 3004.18,815.93 U4.1@3004.39,815.72
  Signal Layer 2 w10: v2@2537.58,582.57 2537.58,523 J6.1@2418.87,404.3 2462.26,360.91 3232.91,360.91 J5.1@3514,642 J8.1@3514,767.49 2985.77,767.49 2969.7,783.56 v2(2969.7,816.13)
  Signal Layer 2 w25: v2(948.17,1012.39) 948.17,1038.75 1015.29,1105.88 1032.07,1105.88 1042.42,1116.23 1062.22,1116.23 1070.97,1124.98 1195.64,1124.98 1568.61,752 1815.32,752 J7.2@1923.8,643.52 2163.02,404.3 J6.1@2418.87,404.3
  other v2: 1189.14,1167.59
"ADC IN": C18.1 R24.2 U6.26 | length 148.8
  Top Layer w10: C18.1@1595.22,1195.89 R24.2@1678.09,1195.89 ; U6.26@1596.71,1129.95 C18.1@1596.71,1195.89
Batt_In: C4.1 D1.1 J1.1 Q1.1 Q1.2 Q1.3 R1.2 TP1.1 U2.6 | length 75.5
  Top Layer w10: U2.6@1182.93,1533.57 1182.93,1600.32 C4.1@1189.14,1606.53
  other v1: 637.98,1621.22 637.98,1651.22 637.98,1681.22 637.98,1711.22 637.98,1741.22 1113.13,1751.18 1143.13,1751.18 637.98,1771.22 1113.13,1781.18 1143.13,1781.18 637.98,1801.22 1113.13,1811.18 1143.13,1811.18 637.98,1835.31 1113.13,1841.18 1143.13,1841.18 637.98,1865.31 1113.13,1871.18 1143.13,1871.18 637.98,1895.31 1113.13,1901.18 637.98,1925.31 637.98,1955.31 637.98,1985.31 637.98,2015.31 637.98,2045.31
  other v2: 84,1644 981.4,1675.22 819,1996 1030.74,1996 1194.43,1996 282,2116 439.33,2116 669,2144 1030.74,2144 1194.43,2144 74,2287 210.98,2287 442.91,2287 1030.74,2287 1194.43,2287
BSL_Invoke: TP15.1 U6.22 | length 449.7
  Top Layer w10: U6.22@1641.99,1064.99 1755.71,1064.99 v2(1772.89,1082.17) ; TP15.1@1789.96,777.56 v2(1789.96,837.8)
  Bottom Layer w10: v2(1772.89,1082.17) 1789.96,1065.1 v2(1789.96,837.8)
BST: C6.2 U3.12 | length 127.6
  Top Layer w10: U3.12@2683.86,1277.07 2684.76,1277.97 2684.76,1304.21 2684.76,1309.8 2693.45,1318.48 2711.8,1318.48 2756.27,1362.95 C6.2@2756.27,1363.93
FAULT_ON_LED: R28.2 U6.13 | length 1152.1
  Top Layer w10: U6.13@1557.34,949.16 1557.34,838.78 1457.78,739.21 1457.78,413.98 1499.87,371.88 1644.28,371.88 1675.62,340.54 1802.71,340.54 1803.04,340.21 R28.2@2002.87,340.21
FETGOOD: R7.1 R25.1 U2.3 | length 671.5
  Top Layer w10: v2(1107.89,1300.89) 1107.89,1257.35 R7.1@1109.45,1255.79 ; U2.3@1182.93,1431.21 1183.1,1431.04 1183.1,1391.36 v2(1183.26,1391.19) ; R25.1@1508.13,1258.88 1510.35,1261.1 v2(1510.35,1299.7)
  Bottom Layer w10: v2(1183.26,1391.19) 1107.89,1315.82 v2(1107.89,1300.89) 1110.89,1297.89 1184.25,1297.89 1207.71,1321.36 1488.69,1321.36 v2(1510.35,1299.7)
FETS_DRAIN: C1.2 C2.1 Q1.5 Q2.5 R2.1 R4.2 R5.1 TP3.1 U1.1 U1.2 U2.8 U3.18 | length 2048.9
  Top Layer w10: v2(724.83,1033.07) 724.83,982.37 C1.2@727.34,979.86 776.18,979.86 793.92,962.12 U1.1@796.87,962.12 U1.2@796.87,936.53 ; U2.8@1131.75,1533.57 v2(1131.75,1564.23) ; 2265,1537 2276.36,1525.64 2276.36,1299.98 R2.1@2278.58,1297.76 2278.58,1150.95 2321.06,1108.47 R5.1@2322.04,1108.47 ; 2293.71,1548.16 2293.71,1533.32 2293.87,1533.16 2293.87,1445.63 2385.41,1354.09 2526.63,1354.09 2565.75,1314.98 U3.18@2565.75,1277.07
  Signal Layer 2 w10: v2(724.83,1033.07) 1131.75,1439.99 1131.75,1578.33 1163.53,1610.11 1247.52,1610.11 1305.86,1668.45
  Bottom Layer w10: 2261.69,1674.39 2273.72,1662.36
  other v1: 1335.86,1658.45 1365.86,1658.45 1395.86,1658.45 1425.86,1658.45 1455.86,1658.45 1485.86,1658.45 1515.86,1658.45 2021.12,1658.45 2051.12,1658.45 2081.12,1658.45 2111.12,1658.45 2141.12,1658.45 2171.12,1658.45 2201.12,1658.45 2231.12,1658.45 2261.12,1658.45 1305.86,1688.45 1335.86,1688.45 1365.86,1688.45 1395.86,1688.45 1425.86,1688.45 1455.86,1688.45 1485.86,1688.45 1515.86,1688.95 2021.12,1688.95 2051.12,1688.95 2081.12,1688.95 2111.12,1688.95 2141.12,1688.95 2171.12,1688.95 2201.12,1688.95 2231.12,1688.95 2261.12,1688.95 1275.86,1718.45 1305.86,1718.45 1335.86,1718.45 1365.86,1718.45 1395.86,1718.45 1425.86,1718.45 1455.86,1718.45 1485.86,1718.45 1515.86,1718.45 2021.12,1718.45 2051.12,1718.45 2081.12,1718.45 2111.12,1718.45 2141.12,1718.45 2171.12,1718.45 2201.12,1718.45 2231.12,1718.45 2261.12,1718.45 1455.86,1752 1485.86,1752 1515.86,1753.03 2021.12,1753.03 2051.12,1753.03 2081.12,1753.03 1455.86,1782 1485.86,1782 1515.86,1781.59 2021.12,1781.59 2051.12,1781.59 2081.12,1781.59 1455.86,1812 1485.86,1812 1515.86,1813.03 2021.12,1813.03 2051.12,1813.03 2081.12,1813.03 1455.86,1842 1485.86,1842 1515.86,1841.59 2021.12,1841.59 2051.12,1841.59 2081.12,1841.59 1455.86,1872 1485.86,1872 1515.86,1873.03 2021.12,1873.03 2051.12,1873.03 2081.12,1873.03 1455.86,1902 1485.86,1902 1515.86,1901.59 2021.12,1901.59 2051.12,1901.59 2081.12,1901.59 1275.86,1936.09 1305.86,1936.09 1335.86,1936.09 1365.86,1936.09 1395.86,1936.09 1425.86,1936.09 1455.86,1936.09 1485.86,1936.09 1515.86,1936.09 2021.12,1936.09 2051.12,1936.09 2081.12,1936.09 2111.12,1936.09 2141.12,1936.09 2171.12,1936.09 2201.12,1936.09 2231.12,1936.09 2261.12,1936.09 1515.86,1965.14 2021.12,1965.14 2051.12,1965.14 2081.12,1965.14 2111.12,1965.14 2141.12,1965.14 2171.12,1965.14 2201.12,1965.14 2231.12,1965.14 2261.12,1965.14 1275.86,1966.09 1305.86,1966.09 1335.86,1966.09 1365.86,1966.09 1395.86,1966.09 1425.86,1966.09 1455.86,1966.09 1485.86,1966.09 1275.86,1996.09 1305.86,1996.09 1335.86,1996.09 1365.86,1996.09 1395.86,1996.09 1425.86,1996.09 1455.86,1996.09 1485.86,1996.09 1515.86,1996.09 2021.12,1996.09 2051.12,1996.09 2081.12,1996.09 2111.12,1996.09 2141.12,1996.09 2171.12,1996.09 2201.12,1996.09 2231.12,1996.09 2261.12,1996.09
  other v2: 1596.71,1584 1998.03,1584 1779.24,1702.71 1850.39,1956.39 1547.5,2075 1288.26,2144 1628.07,2219.48 1288.26,2287
FETS_SOURCE: C6.1 C13.1 Q2.1 Q2.2 Q2.3 R11.1 R14.2 U3.13 U3.17 U5.8 | length 1349.8
  Top Layer w10: 2314.39,1554.37 2314.39,1450.39 2392.81,1371.97 2534.03,1371.97 2585.43,1320.57 U3.17@2585.43,1277.07 ; U3.13@2664.17,1277.07 2664.17,1327.43 2721.3,1384.55 2721.3,1421.55 ; C6.1@2758.45,1430.31 C6.1@2758.45,1431.3 ; R14.2@2850.43,1797.74 2908.48,1797.74 v2(2929.33,1776.89) ; v2(2997.5,1275.47) 3023,1275.47 3048.68,1249.8 U5.8@3048.68,1220.83
  Bottom Layer w10: v2(2929.33,1776.89) 2929.33,1343.01 2996.86,1275.47 v2(2997.5,1275.47)
  other v1: 2822.21,1711.25 2852.21,1711.25 2882.21,1711.25 2336.79,1716.89 2366.79,1716.89 2396.79,1716.89 2685.46,1736 2715.46,1736 2685.46,1766 2715.46,1766 2396.79,1776.89 2685.46,1796 2715.46,1796 2396.79,1806.39 2685.46,1826 2715.46,1826 2396.79,1835.89 2685.46,1856 2715.46,1856 2822.21,1887.82 2852.21,1887.82 2882.21,1887.82
  other v2: 2808,1444 2886.37,1576.45 2544,1649.73 2544,1971 2736.97,1971 2701,2067.46 2913.11,2067.46 2824.94,2068 2445.02,2174.96 2472.78,2174.96 2744.61,2208.76 2913.11,2208.76 2445.02,2219.48 2472.78,2219.48
FLT: R12.1 R23.1 R30.1 U3.5 | length 1053.9
  Top Layer w10: R23.1@2101.3,1281.53 2131.09,1281.53 v2(2245.03,1167.59) ; R12.1@2531.62,779.97 2605.13,779.97 2605.7,780.54 v2(2605.7,915.35) 2605.41,915.65 2605.41,1103.55 U3.5@2605.12,1103.84
  Bottom Layer w10: v2(2245.03,1167.59) 2332.37,1167.59 2584.6,915.35 v2(2605.7,915.35)
Fuse_Channel_Indicator_LED: R29.2 U6.9 | length 1194.3
  Top Layer w10: R29.2@689.94,190.23 691.91,190.23 822.13,320.45 950.48,320.45 1067.44,437.41 1067.44,519.25 1090.96,542.77 1160.22,542.77 1478.6,861.15 U6.9@1478.6,940.98
Fuse_Channel_SW: S2.2 U6.10 | length 599.4
  Top Layer w10: S2.2@1151.41,486.59 1189.72,524.89 1203.53,524.89 1404.15,725.52 1404.15,761.42 1498.28,855.55 U6.10@1498.28,934.17
"Gate 1": Q2.4 R3.2 R6.2 TP4.1 | length 766.3
  Top Layer w10: TP4.1@2484.75,1439.47 2493.66,1448.39 2537.39,1448.39 2551.22,1462.21 R3.2@2599.52,1462.21
  Top Layer w20: Q2.4@2342.61,1902.27 v4(2342.61,1945.16)
  Bottom Layer w20: v4@2357.22,1945.67 2636.7,1666.2 v4(2636.7,1462.21)
"Gate 1 PD": R6.1 U3.14 | length 134
  Top Layer w10: U3.14@2644.49,1277.07 2644.49,1365.37 2676.11,1396.99 R6.1@2676.11,1397.98
"Gate 1 PU": R3.1 U3.15 | length 132.6
  Top Layer w10: R3.1@2599.52,1399.22 2599.52,1398.24 2624.8,1372.95 U3.15@2624.8,1277.07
